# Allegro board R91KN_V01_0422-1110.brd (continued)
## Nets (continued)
GND: C8.2(B) C14.2(B) C20.2(B) C21.2(B) C27.2(B) C33.2(B) C34.1(A) C35.2(B) C43.2(B) C44.2(B) C47.2(B) C53.1(A) C57.2(B) C58.2(B) C59.2(B) C61.2(B) C62.2(B) C63.2(B) C64.2(B) C66.2(B) C67.2(B) C68.2(B) C70.2(B) C71.2(B) C73.2(B) C74.2(B) C75.2(B) C77.2(B) C78.2(B) C79.2(B) C80.2(B) C82.2(B) C83.2(B) C85.2(B) C86.2(B) C87.2(B) C88.2(B) C89.2(B) C90.2(B) C91.2(B) C92.2(B) C93.2(B) C120.2(B) C121.2(B) C122.2(B) C123.2(B) C124.2(B) C125.2(B) C126.2(B) C127.2(B) C128.2(B) C129.2(B) C130.2(B) C131.2(B) C132.2(B) C133.2(B) C134.2(B) C135.2(B) C136.2(B) C137.2(B) C138.2(B) C139.2(B) C140.2(B) C141.2(B) C142.2(B) C143.2(B) C144.2(B) C145.2(B) C146.2(B) C147.2(B) C148.2(B) C149.2(B) C150.2(B) C151.2(B) C152.2(B) C153.2(B) C154.2(B) C155.2(B) C156.2(B) C158.2(B) C161.2(B) C162.2(B) C163.2(B) C164.2(B) C165.2(B) C167.2(B) C168.2(B) C169.2(B) C170.2(B) C171.2(B) C172.2(B) C173.2(B) C174.2(B) C175.2(B) C176.2(B) C177.2(B) C179.2(B) C180.2(B) C181.2(B) C182.2(B) C183.2(B) C184.2(B) C185.2(B) C186.2(B) C187.2(B) C188.2(B) C189.2(B) C190.2(B) C193.2(B) C194.2(B) C195.2(B) C196.2(B) C295.2(B) C297.2(B) C300.1(A) C301.1(A) C302.1(A) C303.1(A) C304.1(A) C305.1(A) C306.1(A) C307.1(A) C308.1(A) C309.1(A) C310.1(A) C311.1(A) C312.1(A) C313.1(A) C314.1(A) C315.1(A) C316.1(A) C317.1(A) C318.1(A) C319.1(A) C320.1(A) C321.1(A) C322.1(A) C323.1(A) C324.1(A) C325.1(A) C326.1(A) C327.1(A) C328.1(A) C329.1(A) C330.1(A) C331.1(A) C332.1(A) C333.1(A) C334.1(A) C335.1(A) C336.1(A) C337.1(A) C338.1(A) C339.1(A) C340.1(A) C341.1(A) C342.1(A) C343.1(A) C344.1(A) C345.1(A) C346.1(A) C347.1(A) C348.1(A) C349.1(A) C350.1(A) C351.1(A) C352.1(A) C353.1(A) C354.1(A) C355.2(B) C356.2(B) C357.2(B) C358.2(B) C359.2(B) C360.2(B) C361.2(B) C362.2(B) C363.2(B) C364.2(B) C365.2(B) C366.2(B) C367.2(B) C368.2(B) C369.2(B) C370.2(B) C371.2(B) C372.2(B) C373.2(B) C374.2(B) C375.2(B) C376.2(B) C377.2(B) C378.2(B) C379.2(B) C380.2(B) C381.2(B) C382.2(B) C383.2(B) C384.1(A) C385.1(A) C386.1(A) C410.2 C411.2 C413.2(B) C438.2(B) C448.2(B) C463.2(B) C486.2(B) C487.2(B) C488.2(B) C489.2(B) C499.2(B) C500.2(B) C603.2(B) C606.2(B) C608.1(A) C609.2(B) C615.2(B) C616.2(B) C617.2(B) C619.2(B) C620.2(B) C621.2(B) C623.2(B) C624.2(B) C625.2(N) C626.2(N) C629.2(B) C630.2(B) C631.2(N) C633.2(B) C703.2(B) C706.2(B) C708.2(B) C715.2(B) C716.2(B) C717.2(B) C718.2(B) C719.2(B) C723.2(B) C724.2(B) C725.2(B) C726.2(N) C727.2(B) C728.1(A) C729.2(N) C730.2(N) C800.1(A) C801.1(A) C841.2(B) C843.2(B) C846.2(B) C851.2(B) C852.2(B) C854.2(B) C856.2(B) C858.2(B) C861.2(B) C862.2(B) C864.2(B) C866.2(B) C868.2(B) C1001.2(B) C1002.2(B) C1003.2(B) C1004.2(B) C1005.2(B) C1006.2(B) C1007.2(B) C1008.2(B) C1010.2(B) C1011.2(B) C1050.2(B) C1051.2(B) C1052.2(B) C1054.2(B) C1055.2(B) C1500.2(B) C1501.1(A) C1502.1(A) C1503.2(B) C1504.1(A) C1505.1(A) C1506.2(B) C1507.1(A) C1508.1(A) C1624.2(B) C1999.1(A) C2001.2(B) C2002.2(B) C2003.2(B) C2004.2(B) C2005.2(B) C2006.2(B) C2509.2(B) C2510.1(A) C2511.1(A) C2512.2(B) C2513.1(A) C2514.1(A) C2515.2(B) C2516.1(A) C2517.1(A) C2540.2(B) C2722.2(B) C3600.2(B) C3608.2(B) C4001.2(B) C4002.2(B) C4003.2(B) C4008.2(B) C4015.2(B) C4020.2(B) C4070.2(B) C4071.2(B) C4100.2(B) C4102.2(B) C4400.2(B) C4401.2(B) C4402.2(B) D1000.2(A) D1001.2(A) D1002.2(A) D1003.2(A) D1004.2(A) D1005.2(A) D1006.2(A) D1600.3(GND) D1600.8(GND1) D1601.3(GND) D1601.8(GND1) D1602.3(GND) D1602.8(GND1) D1603.3(GND) D1603.8(GND1) D2500.2(A) D2501.2(A) D2502.2(A) D2503.3(GND) D2503.8(GND1) D2504.3(GND) D2504.8(GND1) D4401.3(GND) D4401.8(GND1) D4402.3(GND) D4402.8(GND1) D4403.2(A) D4404.2(A) D4405.2(A) D4406.2(A) HS2.1(P1) HS2.2(P2) HS2.3(P3) HS2.4(P4) HS2.5(P5) HS2.6(P6) HS2.7(P7) HS2.8(P8) HS2.9(P1) HS2.10(P2) HS2.11(P3) HS2.12(P4) HS2.13(P5) HS2.14(P6) HS2.15(P7) HS2.16(P8) HS2.17(P1) HS2.18(P2) HS2.19(P3) HS2.20(P4) HS2.21(P5) HS2.22(P6) HS2.23(P7) HS2.24(P8) HS2.25(P1) HS2.26(P2) HS2.27(P3) HS2.28(P4) HS2.29(P5) HS2.30(P6) HS2.31(P7) HS2.32(P8) J1601.3(TMDS_DATA2/4_SHIELD) J1601.11(TMDS_DATA1/3_SHIELD) J1601.15(GND[0]) J1601.19(TMDS_DATA0/5_SHIELD) J1601.22(TMDS_CLOCK_SHIELD) J1601.25(CASE) J1601.26(CASE#M2) J1601.27(CASE#M3) J1601.28(CASE#M4) J1601.29(CASE#M5) J1601.30(CASE#M6) J1601.C5(ANALOG_GND) J1601.C6(ANALOG_GND#C6) J2501.2(GND_0) J2501.5(GND_1) J2501.8(GND_2) J2501.11(GND_3) J2501.16(GND_6) J2501.19(PWR_RTN) J2501.G1 J2501.G2 J2501.G3 J2501.G4 J4004.4(P4) MC130.2(B) MC131.2(B) MC132.2(B) MC133.2(B) MC174.2(B) MC175.2(B) MC176.2(B) MC177.2(B) MC196.2(B) MC364.2(B) MC365.2(B) MC366.2(B) MC367.2(B) MC368.2(B) MC369.2(B) MC378.2(B) MC379.2(B) MC380.2(B) MC381.2(B) MC382.2(B) MC383.2(B) MJ1001.5(VSS) MJ1001.6(VSS#6) MJ1001.7(VSS#7) MJ1001.8(VSS#8) MJ1001.10(VSS#10) MJ1001.16(CASE) MJ1001.17(CASE#17) MJ2501.2 MJ2501.5 MJ2501.8 MJ2501.11 MJ2501.17 MJ2501.20(GND#20) MJ2501.21(GND#21) MJ2501.22(GND#22) MJ2501.23(GND#23) MPCIE1.A4(GND_A4) MPCIE1.A12(GND_A12) MPCIE1.A15(GND_A15) MPCIE1.A18(GND_A18) MPCIE1.A20(GND_A20) MPCIE1.A23(GND_A23) MPCIE1.A24(GND_A24) MPCIE1.A27(GND_A27) MPCIE1.A28(GND_A28) MPCIE1.A31(GND_A31) MPCIE1.A34(GND_A34) MPCIE1.A37(GND_A37) MPCIE1.A38(GND_A38) MPCIE1.A41(GND_A41) MPCIE1.A42(GND_A42) MPCIE1.A45(GND_A45) MPCIE1.A46(GND_A46) MPCIE1.A49(GND_A49) MPCIE1.A51(GND_A51) MPCIE1.A54(GND_A54) MPCIE1.A55(GND_A55) MPCIE1.A58(GND_A58) MPCIE1.A59(GND_A59) MPCIE1.A62(GND_A62) MPCIE1.A63(GND_A63) MPCIE1.A66(GND_A66) MPCIE1.A67(GND_A67) MPCIE1.A70(GND_A70) MPCIE1.A71(GND_A71) MPCIE1.A74(GND_A74) MPCIE1.A75(GND_A75) MPCIE1.A78(GND_A78) MPCIE1.A79(GND_A79) MPCIE1.A82(GND_A82) MPCIE1.B4(GND_B4) MPCIE1.B7(GND_B7) MPCIE1.B13(GND_B13) MPCIE1.B16(GND_B16) MPCIE1.B18(GND_B18) MPCIE1.B21(GND_B21) MPCIE1.B22(GND_B22) MPCIE1.B25(GND_B25) MPCIE1.B26(GND_B26) MPCIE1.B29(GND_B29) MPCIE1.B32(GND_B32) MPCIE1.B35(GND_B35) MPCIE1.B36(GND_B36) MPCIE1.B39(GND_B39) MPCIE1.B40(GND_B40) MPCIE1.B43(GND_B43) MPCIE1.B44(GND_B44) MPCIE1.B47(GND_B47) MPCIE1.B49(GND_B49) MPCIE1.B52(GND_B52) MPCIE1.B53(GND_B53) MPCIE1.B56(GND_B56) MPCIE1.B57(GND_B57) MPCIE1.B60(GND_B60) MPCIE1.B61(GND_B61) MPCIE1.B64(GND_B64) MPCIE1.B65(GND_B65) MPCIE1.B68(GND_B68) MPCIE1.B69(GND_B69) MPCIE1.B72(GND_B72) MPCIE1.B73(GND_B73) MPCIE1.B76(GND_B76) MPCIE1.B77(GND_B77) MPCIE1.B80(GND_B80) MR43.1(A) MR44.1(A) MR45.1(A) MR46.1(A) MR47.1(A) MR48.1(A) MR49.1(A) MR50.1(A) MR51.1(A) MR52.1(A) MR53.1(A) MR54.1(A) MR55.1(A) MR56.1(A) MR57.2(B) MR58.1(A) MR70.1(A) MR71.1(A) MR1240.1(A) MR1241.1(A) MT200.1(P2) MT200.2(P3) MT200.3(P4) MT200.4(P5) MT200.5(P6) MT200.6(P7) MT200.7(P8) MT200.8(P9) MU861.8(GND#8) MU861.9(GND#9) Q603.1(S1) Q603.2(S2) Q603.3(S3) Q703.1(S1) Q703.2(S2) Q703.3(S3) Q840.2(E) Q841.2(E) Q842.2(E) Q851.2(E) Q852.2(E) Q1200.2(S) Q1201.2(S) Q1601.2(S) Q1803.2(E) Q1804.2(S) Q2701.2(S) Q4006.2(E) Q4007.2(E) Q4009.2(E) Q4010.2(E) Q4011.2(E) Q4013.2(E) Q4016.2(E) Q4050.2(E) Q4100.2(E) Q4102.3(C) Q4103.3(E) Q4401.2(E) R7.1(A) R9.2(B) R12.1(A) R22.1(A) R23.2(B) R32.1(A) R35.2(B) R37.2(B) R39.2(B) R60.2(B) R76.1(A) R202.2(B) R204.2(B) R206.2(B) R208.2(B) R210.2(B) R212.2(B) R214.2(B) R216.2(B) R217.2(B) R218.2(B) R219.2(B) R220.2(B) R229.1(A) R230.1(A) R292.2(B) R294.2(B) R296.2(B) R297.2(B) R298.2(B) R301.2(B) R609.1(A) R610.1(A) R615.2(B) R709.1(A) R710.2(B) R715.2(B) R851.2(B) R853.2(B) R854.2(B) R864.2(B) R1001.2(B) R1002.2(B) R1003.2(B) R1027.2(B) R1028.2(B) R1029.2(B) R1500.2(B) R1617.2(B) R2001.2(B) R2002.2(B) R2003.2(B) R2027.2(B) R2028.2(B) R2029.2(B) R2500.2(B) R2522.2(B) R2524.2(B) R2526.2(B) R2530.2(B) R3600.1(A) R4039.2(B) R4043.2(B) R4047.2(B) R4053.2(B) R4061.1(A) R4063.2(B) R4072.2(B) R4073.2(B) R4076.2(B) R4077.2(B) R4106.2(B) R4108.2(B) R4110.2(B) R4111.2(B) R4113.2(B) R4403.2(B) R4408.1(A) R4409.2(B) SW4001.3(A2) SW4001.4(A2) SW4002.3(A2) TP503.1 U1.A3(GND#1) U1.A30(GND#2) U1.A32(VSS_MECH#1) U1.AA1(DP_VSSR#AA1) U1.AA13(GND#3) U1.AA16(GND#84) U1.AA27(PCIE_VSS#1) U1.AB6(GND#6) U1.AB10(GND#4) U1.AB15(GND#5) U1.AB24(PCIE_VSS#2) U1.AB32(PCIE_VSS#3) U1.AC9(GND#7) U1.AC17(TSVSS) U1.AC19(NC#AC19) U1.AC24(PCIE_VSS#4) U1.AC26(PCIE_VSS#5) U1.AC27(PCIE_VSS#6) U1.AD6(GND#8) U1.AD8(GND#9) U1.AD23(VSS1DI) U1.AD25(PCIE_VSS#7) U1.AD32(PCIE_VSS#8) U1.AE1(DP_VSSR#AE1) U1.AE3(DP_VSSR#AE3) U1.AE7(GND#10) U1.AE14(DPLL_PVSS) U1.AE19(TSVSSQ) U1.AE22(AVSSQ) U1.AE27(PCIE_VSS#9) U1.AF10(DP_VSSR#AF10) U1.AF19(DP_VSSR#AF19) U1.AF20(DP_VSSR#AF20) U1.AF23(DP_VSSR#AF23) U1.AF32(PCIE_VSS#10) U1.AG1(DP_VSSR#AG1) U1.AG6(DP_VSSR#AG6) U1.AG7(DP_VSSR#AG7) U1.AG9(DP_VSSR#AG9) U1.AG11(DP_VSSR#AG11) U1.AG12(GND#11) U1.AG14(DP_VSSR#AG14) U1.AG23(DP_VSSR#AG23) U1.AG27(PCIE_VSS#11) U1.AH5(DP_VSSR#AH5) U1.AH8(DP_VSSR#AH8) U1.AH10(GND#12) U1.AH14(DP_VSSR#AH14) U1.AH28(GND#13) U1.AH32(PCIE_VSS#12) U1.AM1(VSS_MECH#2) U1.AM6(DP_VSSR#AM6) U1.AM8(DP_VSSR#AM8) U1.AM14(DP_VSSR#AM14) U1.AM16(DP_VSSR#AM16) U1.AM18(DP_VSSR#AM18) U1.AM20(DP_VSSR#AM20) U1.AM22(DP_VSSR#AM22) U1.AM24(DP_VSSR#AM24) U1.AM32(VSS_MECH#3) U1.B6(GND#23) U1.B8(GND#24) U1.B10(GND#14) U1.B12(GND#15) U1.B14(GND#16) U1.B16(GND#17) U1.B18(GND#18) U1.B20(GND#19) U1.B22(GND#20) U1.B24(GND#21) U1.B26(GND#22) U1.C1(GND#25) U1.C32(GND#26) U1.E28(GND#27) U1.F2(GND#33) U1.F6(GND#38) U1.F8(GND#39) U1.F10(GND#28) U1.F12(GND#29) U1.F14(GND#30) U1.F16(GND#31) U1.F18(GND#32) U1.F20(GND#34) U1.F22(GND#35) U1.F24(GND#36) U1.F26(GND#37) U1.G8(GND#43) U1.G10(GND#40) U1.G27(GND#41) U1.G31(GND#42) U1.H2(GND#46) U1.H6(GND#48) U1.H14(GND#44) U1.H17(GND#45) U1.H20(GND#47) U1.J7(SPVSS) U1.J27(GND#49) U1.J31(GND#50) U1.K2(GND#52) U1.K6(GND#54) U1.K11(GND#51) U1.K22(GND#53) U1.K28(PCIE_VSS#13) U1.K32(PCIE_VSS#14) U1.L27(PCIE_VSS#15) U1.M6(GND#55) U1.M32(PCIE_VSS#16) U1.N11(NC#N11) U1.N12(NC#N12) U1.N13(GND#56) U1.N16(GND#57) U1.N18(GND#58) U1.N21(GND#59) U1.N25(PCIE_VSS#17) U1.N27(PCIE_VSS#18) U1.P6(GND#60) U1.P9(GND#61) U1.P25(PCIE_VSS#19) U1.P32(PCIE_VSS#20) U1.R11(GND#86) U1.R12(GND#62) U1.R15(GND#63) U1.R17(GND#64) U1.R20(GND#65) U1.R27(PCIE_VSS#21) U1.T6(GND#70) U1.T11(GND#85) U1.T13(GND#66) U1.T16(GND#67) U1.T18(GND#68) U1.T21(GND#69) U1.T25(PCIE_VSS#22) U1.T32(PCIE_VSS#23) U1.U1(DP_VSSR#U1) U1.U3(DP_VSSR#U3) U1.U9(GND#74) U1.U15(GND#71) U1.U17(GND#72) U1.U20(GND#73) U1.U25(PCIE_VSS#24) U1.U27(PCIE_VSS#25) U1.V6(DP_VSSR#V6) U1.V13(GND#75) U1.V16(GND#76) U1.V18(GND#77) U1.V32(PCIE_VSS#26) U1.W1(DP_VSSR#W1) U1.W25(PCIE_VSS#27) U1.W26(PCIE_VSS#28) U1.W27(PCIE_VSS#29) U1.Y6(DP_VSSR#Y6) U1.Y10(GND#78) U1.Y15(GND#79) U1.Y17(GND#80) U1.Y20(GND#81) U1.Y25(PCIE_VSS#30) U1.Y32(PCIE_VSS#31) U2.4(GND) U4.3(GND) U12.2(GND_27M) U12.6(GND_100M) U12.11(GND_PAD) U201.A9(VSS#A9) U201.B1(VSSQ#B1) U201.B3(VSS#B3) U201.B9(VSSQ#B9) U201.D1(VSSQ#D1) U201.D8(VSSQ#D8) U201.E1(VSS#E1) U201.E2(VSSQ#E2) U201.E8(VSSQ#E8) U201.F9(VSSQ#F9) U201.G1(VSSQ#G1) U201.G8(VSS#G8) U201.G9(VSSQ#G9) U201.J2(VSS#J2) U201.J8(VSS#J8) U201.M1(VSS#M1) U201.M9(VSS#M9) U201.P1(VSS#P1) U201.P9(VSS#P9) U201.T1(VSS#T1) U201.T9(VSS#T9) U202.A9(VSS#A9) U202.B1(VSSQ#B1) U202.B3(VSS#B3) U202.B9(VSSQ#B9) U202.D1(VSSQ#D1) U202.D8(VSSQ#D8) U202.E1(VSS#E1) U202.E2(VSSQ#E2) U202.E8(VSSQ#E8) U202.F9(VSSQ#F9) U202.G1(VSSQ#G1) U202.G8(VSS#G8) U202.G9(VSSQ#G9) U202.J2(VSS#J2) U202.J8(VSS#J8) U202.M1(VSS#M1) U202.M9(VSS#M9) U202.P1(VSS#P1) U202.P9(VSS#P9) U202.T1(VSS#T1) U202.T9(VSS#T9) U401.A9(VSS#A9) U401.B1(VSSQ#B1) U401.B3(VSS#B3) U401.B9(VSSQ#B9) U401.D1(VSSQ#D1) U401.D8(VSSQ#D8) U401.E1(VSS#E1) U401.E2(VSSQ#E2) U401.E8(VSSQ#E8) U401.F9(VSSQ#F9) U401.G1(VSSQ#G1) U401.G8(VSS#G8) U401.G9(VSSQ#G9) U401.J2(VSS#J2) U401.J8(VSS#J8) U401.M1(VSS#M1) U401.M9(VSS#M9) U401.P1(VSS#P1) U401.P9(VSS#P9) U401.T1(VSS#T1) U401.T9(VSS#T9) U402.A9(VSS#A9) U402.B1(VSSQ#B1) U402.B3(VSS#B3) U402.B9(VSSQ#B9) U402.D1(VSSQ#D1) U402.D8(VSSQ#D8) U402.E1(VSS#E1) U402.E2(VSSQ#E2) U402.E8(VSSQ#E8) U402.F9(VSSQ#F9) U402.G1(VSSQ#G1) U402.G8(VSS#G8) U402.G9(VSSQ#G9) U402.J2(VSS#J2) U402.J8(VSS#J8) U402.M1(VSS#M1) U402.M9(VSS#M9) U402.P1(VSS#P1) U402.P9(VSS#P9) U402.T1(VSS#T1) U402.T9(VSS#T9) U403.2(GND) U403.4(TAB) U601.3(GND) U701.3(GND) U851.8(GND#8) U851.9(GND#9) U861.8(GND#8) U861.9(GND#9) U1999.1(C) U1999.4(C) U1999.7(GND) U4001.6(GND) U4001.11(EPAD1) U4050.3(GND) U4050.15(EPAD)
VDD33_27M: B72.2(B) C90.1(A) U12.8(VDD_27M)
VDD33_100M: B71.2(B) C91.1(A) U12.4(VDD_100M)
VDDC_BOOT: C605.1(A) D601.1(K) U601.1(BOOT)
VDDC_EN: C611.1(A) C612.1(A) Q852.3(C) Q4010.3(C) U601.7(COMP)
VDDC_ENB: C4401.1(A) Q4010.1(B) R4051.1(A) R4053.1(A)
VDDC_FB: R610.2(B) R611.1(A) R613.1(A) R614.1(A) R1225.1(A) R1226.1(A) R4078.2(B) U601.6(FB)
VDDC_FB_IN1: Q1200.3(D) R1226.2(B)
VDDC_FB_IN2: Q1201.3(D) R1225.2(B)
VDDC_FB_TRACE: NS600.2(N2) R600.1(A)
VDDC_LGATE: Q603.4(G4) R622.2(B)
VDDC_LGATE_CTR: R615.1(A) R622.1(A) U601.4(LGATE)
VDDC_PHASE: C605.2(B) L601.1 Q601.1(S1) Q601.2(S2) Q601.3(S3) Q603.5(D5) Q603.6(D6) Q603.7(D7) Q603.8(D8) Q603.9(D9) R619.2(B) U601.8(PHASE)
VDDC_SV: C613.1(A) R600.2(B) R611.2(B)
VDDC_UGATE: Q601.4(G4) R621.2(B)
VDDC_UGATE_CTR: R621.1(A) U601.2(UGATE)
VDDC_VCC: C603.1(A) R607.2(B) U601.5(VCC)
+DPAB_18: B2503.2(B) C2509.1(A) C2510.2(B) C2511.2(B) C2512.1(A) C2513.2(B) C2514.2(B) U1.AE11(DPAB_VDD18#3) U1.AE13(DPAB_VDD18#5) U1.AF11(DPAB_VDD18#4) U1.AF13(DPAB_VDD18#6) U1.AG8(DPAB_VDD18#1) U1.AG10(DPAB_VDD18#2)
+DPAB_VDD10: B2505.2(B) C2515.1(A) C2516.2(B) C2517.2(B) U1.AF6(DPAB_VDD10#1) U1.AF7(DPAB_VDD10#2) U1.AF8(DPAB_VDD10#3) U1.AF9(DPAB_VDD10#4)
+DPC_18: B800.2(B) C800.2(B) U1.AC5(DPC_VDD18#2) U1.AC6(DPC_VDD18#3) U1.W6(DPC_VDD18#1)
+DPC_VDD10: B801.2(B) C801.2(B) U1.AA5(DPC_VDD10#1) U1.AA6(DPC_VDD10#2)
+DPEF_18: B1500.2(B) C1500.1(A) C1501.2(B) C1502.2(B) C1503.1(A) C1504.2(B) C1505.2(B) U1.AF16(DPEF_VDD18#5) U1.AG15(DPEF_VDD18#3) U1.AG16(DPEF_VDD18#4) U1.AG17(DPEF_VDD18#6) U1.AG18(DPEF_VDD18#1) U1.AG19(DPEF_VDD18#2)
+DPEF_VDD10: B1502.2(B) C1506.1(A) C1507.2(B) C1508.2(B) U1.AF22(DPEF_VDD10#3) U1.AG20(DPEF_VDD10#1) U1.AG21(DPEF_VDD10#2) U1.AG22(DPEF_VDD10#4)
+DPLL_PVDD: B7.2(B) C59.1(A) C63.1(A) C64.1(A) C88.1(A) U1.AF14(DPLL_PVDD)
+DPLL_VDDC: B8.2(B) C66.1(A) C67.1(A) C68.1(A) U1.AD14(DPLL_VDDC)
+MPV18: B12.2(B) C77.1(A) C78.1(A) C79.1(A) C80.1(A) U1.L8(MPV18)
+MVDD: C120.1(A) C121.1(A) C122.1(A) C123.1(A) C124.1(A) C125.1(A) C126.1(A) C127.1(A) C128.1(A) C129.1(A) C130.1(A) C131.1(A) C132.1(A) C133.1(A) C134.1(A) C135.1(A) C136.1(A) C137.1(A) C138.1(A) C139.1(A) C140.1(A) C141.1(A) C142.1(A) C300.2(B) C301.2(B) C302.2(B) C303.2(B) C304.2(B) C305.2(B) C306.2(B) C307.2(B) C308.2(B) C309.2(B) C310.2(B) C311.2(B) C312.2(B) C313.2(B) C314.2(B) C315.2(B) C316.2(B) C317.2(B) C318.2(B) C319.2(B) C320.2(B) C321.2(B) C322.2(B) C323.2(B) C324.2(B) C325.2(B) C326.2(B) C327.2(B) C328.2(B) C329.2(B) C330.2(B) C331.2(B) C332.2(B) C333.2(B) C334.2(B) C335.2(B) C336.2(B) C337.2(B) C338.2(B) C339.2(B) C340.2(B) C341.2(B) C342.2(B) C343.2(B) C344.2(B) C345.2(B) C346.2(B) C347.2(B) C348.2(B) C349.2(B) C350.2(B) C351.2(B) C352.2(B) C353.2(B) C354.2(B) C355.1(A) C356.1(A) C357.1(A) C358.1(A) C359.1(A) C360.1(A) C361.1(A) C362.1(A) C363.1(A) C364.1(A) C365.1(A) C366.1(A) C367.1(A) C368.1(A) C369.1(A) C370.1(A) C371.1(A) C372.1(A) C373.1(A) C374.1(A) C375.1(A) C376.1(A) C377.1(A) C378.1(A) C379.1(A) C380.1(A) C381.1(A) C382.1(A) C383.1(A) C384.2(B) C385.2(B) C386.2(B) C723.1(A) C724.1(A) C725.1(A) C726.1(P) C727.1(A) C728.2(B) C729.1(P) L701.2 MC130.1(A) MC131.1(A) MC132.1(A) MC133.1(A) MC364.1(A) MC365.1(A) MC366.1(A) MC367.1(A) MC368.1(A) MC369.1(A) MC378.1(A) MC379.1(A) MC380.1(A) MC381.1(A) MC382.1(A) MC383.1(A) MR858.1(A) NS700.1(N1) R201.1(A) R203.1(A) R205.1(A) R207.1(A) R209.1(A) R211.1(A) R213.1(A) R215.1(A) R225.2(B) R227.2(B) R291.1(A) R293.1(A) R302.2(B) R858.1(A) U1.H13(VDDR1#1) U1.H16(VDDR1#2) U1.H19(VDDR1#3) U1.J9(VDDR1#7) U1.J10(VDDR1#4) U1.J23(VDDR1#5) U1.J24(VDDR1#6) U1.K9(VDDR1#11) U1.K10(VDDR1#8) U1.K23(VDDR1#9) U1.K24(VDDR1#10) U1.L11(VDDR1#12) U1.L12(VDDR1#13) U1.L13(VDDR1#14) U1.L20(VDDR1#15) U1.L21(VDDR1#16) U1.L22(VDDR1#17) U201.A1(VDDQ#A1) U201.A8(VDDQ#A8) U201.B2(VDD#B2) U201.C1(VDDQ#C1) U201.C9(VDDQ#C9) U201.D2(VDDQ#D2) U201.D9(VDD#D9) U201.E9(VDDQ#E9) U201.F1(VDDQ#F1) U201.G7(VDD#G7) U201.H2(VDDQ#H2) U201.H9(VDDQ#H9) U201.K2(VDD#K2) U201.K8(VDD#K8) U201.N1(VDD#N1) U201.N9(VDD#N9) U201.R1(VDD#R1) U201.R9(VDD#R9) U202.A1(VDDQ#A1) U202.A8(VDDQ#A8) U202.B2(VDD#B2) U202.C1(VDDQ#C1) U202.C9(VDDQ#C9) U202.D2(VDDQ#D2) U202.D9(VDD#D9) U202.E9(VDDQ#E9) U202.F1(VDDQ#F1) U202.G7(VDD#G7) U202.H2(VDDQ#H2) U202.H9(VDDQ#H9) U202.K2(VDD#K2) U202.K8(VDD#K8) U202.N1(VDD#N1) U202.N9(VDD#N9) U202.R1(VDD#R1) U202.R9(VDD#R9) U401.A1(VDDQ#A1) U401.A8(VDDQ#A8) U401.B2(VDD#B2) U401.C1(VDDQ#C1) U401.C9(VDDQ#C9) U401.D2(VDDQ#D2) U401.D9(VDD#D9) U401.E9(VDDQ#E9) U401.F1(VDDQ#F1) U401.G7(VDD#G7) U401.H2(VDDQ#H2) U401.H9(VDDQ#H9) U401.K2(VDD#K2) U401.K8(VDD#K8) U401.N1(VDD#N1) U401.N9(VDD#N9) U401.R1(VDD#R1) U401.R9(VDD#R9) U402.A1(VDDQ#A1) U402.A8(VDDQ#A8) U402.B2(VDD#B2) U402.C1(VDDQ#C1) U402.C9(VDDQ#C9) U402.D2(VDDQ#D2) U402.D9(VDD#D9) U402.E9(VDDQ#E9) U402.F1(VDDQ#F1) U402.G7(VDD#G7) U402.H2(VDDQ#H2) U402.H9(VDDQ#H9) U402.K2(VDD#K2) U402.K8(VDD#K8) U402.N1(VDD#N1) U402.N9(VDD#N9) U402.R1(VDD#R1) U402.R9(VDD#R9) UNK+MVDD.1
+MVDD_SOURCE: B702.1(A) C715.1(A) C716.1(A) C717.1(A) C718.1(A) C719.1(A) C730.1(P) Q701.5(D5) Q701.6(D6) Q701.7(D7) Q701.8(D8) Q701.9(D9) R702.1(A)
+PCIE_PVDD: B11.2(B) C73.1(A) C74.1(A) C75.1(A) C89.1(A) U1.AM30(PCIE_VDDR#9)
+SPV10: B9.2(B) C70.1(A) C71.1(A) MB9.2(B) U1.H8(SPV10)
+SPV18: B5.2(B) C58.1(A) C61.1(A) C62.1(A) U1.H7(SPV18)
A_B_DAC1: MR1017.1(A) R1001.1(A) R1017.1(A) U1.AH24(B)
A_B_DAC1_F: C1006.1(A) D1002.1(K) J1601.C3(ANALOG_BLUE) L1003.2(B)
A_B_DAC2_F: C2006.1(A) L2003.2(B) MJ1001.3(B)
A_BB_DAC1: MR1029.1(A) R1029.1(A) U1.AG25(BB)
A_G_DAC1: MR1016.1(A) R1002.1(A) R1016.1(A) U1.AL25(G)
A_G_DAC1_F: C1005.1(A) D1001.1(K) J1601.C2(ANALOG_GREEN) L1002.2(B)
A_G_DAC2_F: C2005.1(A) L2002.2(B) MJ1001.2(G)
A_GB_DAC1: MR1028.1(A) R1028.1(A) U1.AJ25(GB)
A_HSYNC_DAC1: MR52.2(B) R52.2(B) U1.AH26(HSYNC) U1999.2(A)
A_HSYNC_DAC1_B: R1010.1(A) U1999.3(Y)
A_HSYNC_DAC1_C: C1007.1(A) MR1018.1(A) R1010.2(B) R1018.1(A)
A_HSYNC_DAC1_R: D1005.1(K) J1601.C4(ANALOG_HYNC) R1018.2(B)
A_HSYNC_DAC2: MR56.2(B) R56.2(B) U1.AL13(GENLK_CLK)
A_HSYNC_DAC2_R: MJ1001.13(HS) MR1018.2(B)
A_R_DAC1: MR1015.1(A) R1003.1(A) R1015.1(A) U1.AM26(R)
A_R_DAC1_F: C1004.1(A) D1000.1(K) J1601.C1(ANALOG_RED) L1001.2(B)
A_R_DAC2_F: C2004.1(A) L2001.2(B) MJ1001.1(R)
A_RB_DAC1: MR1027.1(A) R1027.1(A) U1.AK26(RB)
A_VSYNC_DAC1: MR51.2(B) R51.2(B) U1.AJ27(VSYNC) U1999.5(A)
A_VSYNC_DAC1_B: R1011.1(A) U1999.6(Y)
A_VSYNC_DAC1_C: C1008.1(A) MR1019.1(A) R1011.2(B) R1019.1(A)
A_VSYNC_DAC1_R: D1006.1(K) J1601.8(ANALOG_VSYNC) R1019.2(B)
A_VSYNC_DAC2: MR43.2(B) R43.2(B) U1.AJ13(GENLK_VSYNC)
A_VSYNC_DAC2_R: MJ1001.14(VS) MR1019.2(B)
AUX1_BYPSS_EN: Q1801.1(G) Q1802.1(G) Q1803.3(C) R1804.2(B)
AUX2N: C2541.1(A) U1.AD11(AUX2N)
AUX2P: C2535.1(A) U1.AD13(AUX2P)
B_DAC2: C2003.1(A) L2003.1(A) MR1017.2(B) R2001.1(A)
BA0: U1.J16(MAA_BA0) U201.M2(BA0) U202.M2(BA0) U401.M2(BA0) U402.M2(BA0)
BA1: U1.L15(MAA_BA1) U201.N8(BA1) U202.N8(BA1) U401.N8(BA1) U402.N8(BA1)
BA2: U1.G11(MAA_BA2) U201.M3(BA2) U202.M3(BA2) U401.M3(BA2) U402.M3(BA2)
BB_DAC2: MR1029.2(B) R2029.1(A)
CASA#0: U1.G19(CASA0B) U201.K3(CAS_N) U202.K3(CAS_N)
CASA#1: U1.G16(CASA1B) U401.K3(CAS_N) U402.K3(CAS_N)
CEC1: MJ2501.13 TP1700.1
CEDAR_NC: R72.1(A) U1.AA11(NC#1) U1.AA12(NC#4) U1.U11(NC#3) U1.V11(NC#2) U1.Y11(DVCLK)
CKEA0: U1.K20(CKEA0) U201.K9(CKE) U202.K9(CKE)
CKEA1: U1.J17(CKEA1) U401.K9(CKE) U402.K9(CKE)
CLK_27M: MR75.1(A) NR75.1(A) TR75.1(A) U12.9(27M_OUT)
CLK_100M: R73.1(A) R74.1(A) R75.1(A) U12.5(100M_OUT)
CLKA0: R221.1(A) U1.H26(CLKA0) U201.J7(CK) U202.J7(CK)
CLKA1: R223.1(A) U1.G9(CLKA1) U401.J7(CK) U402.J7(CK)
CLKA#0: R222.2(B) U1.H25(CLKA0B) U201.K7(CK_N) U202.K7(CK_N)
CLKA#1: R224.2(B) U1.H9(CLKA1B) U401.K7(CK_N) U402.K7(CK_N)
CLKTESTA: C94.1(A) U1.K8(CLKTESTA)
CLKTESTB: C95.1(A) U1.L7(CLKTESTB)
CSA#0_0: U1.H22(CSA0B_0) U201.L2(CS_N) U202.L2(CS_N)
CSA#1_0: U1.G13(CSA1B_0) U401.L2(CS_N) U402.L2(CS_N)
CTF2_GAT: Q4400.1(B) R4405.1(A) R4407.2(B)
CTF2_TRIP: C4400.1(A) Q4401.1(B) R4402.1(A) R4403.1(A) R4404.2(B)
CTF2_VCNTL: Q4400.3(C) R4404.1(A) R4406.1(A)
CTF_BYPASS: R4051.2(B) R4052.2(B) R4057.2(B) R4058.2(B) R4062.2(B) R4406.2(B) R4408.2(B)
CTF_FB_CNTL: Q4007.1(B) R4046.1(A)
CTF_GATED2: Q4006.3(C) Q4007.3(C) R4040.2(B) R4044.2(B) R4065.2(B)
CTF_SET2: C4013.2(B) C4014.2(B) Q4008.1(B) Q4014.2(S) R4043.1(A)
CTF_SET3: Q4009.1(B) R4044.1(A)
CTF_TRIP: Q4006.1(B) R4038.2(B) R4039.1(A)
CTF_VCNTL: C4015.1(A) Q4009.3(C) R4045.2(B) R4046.2(B) R4047.1(A) R4052.1(A) R4060.1(A)
CUR_VDDCT_ADJ_0: R4078.1(A) U4050.8(OUT0)
DACT_A0: R4077.1(A) U4050.9(A0)
DACT_A1: MR4076.2(B) R4076.1(A) U4050.11(A1)
DACT_CLK: R4071.2(B) U4050.2(SCL)
DACT_DATA: R4070.2(B) U4050.1(SDA)
DACT_FS0: R4073.1(A) U4050.7(FS0)
DACT_FS1: R4072.1(A) U4050.6(FS1)
DDC1CLK: R2008.2(B) R2009.1(A) U1.AE6(DDC1CLK)
DDC1DATA: R2005.2(B) R2006.1(A) U1.AE5(DDC1DATA)
DDC2CLK: Q1801.2(S) U1.AC11(DDC2CLK)
DDC2DATA: Q1802.2(S) U1.AC13(DDC2DATA)
DDC3CLK: R1008.2(B) R1009.1(A) U1.AD20(DDCCLK_AUX3P)
DDC3DATA: R1005.2(B) R1006.1(A) U1.AC20(DDCDATA_AUX3N)
DDC5CLK_AUX5P: D4404.1(K) MJ2501.15 R2701.2(B) U1.AE16(DDCCLK_AUX5P)
DDC5DATA_AUX5N: D4403.1(K) MJ2501.16 R2703.2(B) U1.AD16(DDCDATA_AUX5N)
DDC6CLK: R4001.1(A) R4017.2(B) R4071.1(A) U1.AC1(DDC6CLK)
DDC6DATA: R4002.1(A) R4018.2(B) R4070.1(A) U1.AC3(DDC6DATA)
DDCCLK_DAC1_R: D1004.1(K) J1601.6(DDC_CLOCK) R1009.2(B)
DDCCLK_DAC2_R: MJ1001.15(MS3) R2009.2(B)
DDCDATA_DAC1_R: D1003.1(K) J1601.7(DDC_DATA) R1006.2(B)
DDCDATA_DAC2_R: MJ1001.12(MS1) R2006.2(B)
DPA_0N: C4404.2(B) D4401.4(C) D4401.7(Y3) J2501.3(ML_LANE_0N)
DPA_0P: C4403.2(B) D4401.5(D) D4401.6(Y4) J2501.1(ML_LANE_0P)
DPA_1N: C4406.2(B) D4401.1(A) D4401.10(Y1) J2501.6(ML_LANE_1N)
DPA_1P: C4405.2(B) D4401.2(B) D4401.9(Y2) J2501.4(ML_LANE_1P)
DPA_2N: C4408.2(B) D4402.4(C) D4402.7(Y3) J2501.9(ML_LANE_2N)
DPA_2P: C4407.2(B) D4402.5(D) D4402.6(Y4) J2501.7(ML_LANE_2P)
DPA_3N: C4410.2(B) D4402.1(A) D4402.10(Y1) J2501.12(ML_LANE_3N)
DPA_3P: C4409.2(B) D4402.2(B) D4402.9(Y2) J2501.10(ML_LANE_3P)
DPA_A0N: C4404.1(A) U1.AK1(TX2M_DPA0N)
DPA_A0P: C4403.1(A) U1.AK3(TX2P_DPA0P)
DPA_A1N: C4406.1(A) U1.AH1(TX1M_DPA1N)
DPA_A1P: C4405.1(A) U1.AH3(TX1P_DPA1P)
DPA_A2N: C4408.1(A) U1.AG5(TX0M_DPA2N)
DPA_A2P: C4407.1(A) U1.AG3(TX0P_DPA2P)
DPA_A3N: C4410.1(A) U1.AF4(TXCAM_DPA3N)
DPA_A3P: C4409.1(A) U1.AF2(TXCAP_DPA3P)
DPA_GND: Q2701.3(D) R2713.2(B) R2714.2(B) R2715.2(B) R2716.2(B) R2717.2(B) R2718.2(B) R2719.2(B) R2720.2(B)
DPAB_CALR: R2500.1(A) U1.AE10(DPAB_CALR)
DPB_0N: C2531.2(B) D2504.4(C) D2504.7(Y3) MJ2501.3 R2714.1(A)
DPB_0P: C2530.2(B) D2504.5(D) D2504.6(Y4) MJ2501.1 R2713.1(A)
DPB_1M: J2501.14(PIN_14) R2526.1(A)
DPB_1N: C2533.2(B) D2504.1(A) D2504.10(Y1) MJ2501.6 R2716.1(A)
DPB_1P: C2532.2(B) D2504.2(B) D2504.9(Y2) MJ2501.4 R2715.1(A)
DPB_2N: C2536.2(B) D2503.4(C) D2503.7(Y3) MJ2501.9 R2718.1(A)
DPB_2P: C2534.2(B) D2503.5(D) D2503.6(Y4) MJ2501.7 R2717.1(A)
DPB_3N: C2538.2(B) D2503.1(A) D2503.10(Y1) MJ2501.12 R2720.1(A)
DPB_3P: C2537.2(B) D2503.2(B) D2503.9(Y2) MJ2501.10 R2719.1(A)
DPB_AUXN: C2541.2(B) D2500.1(K) J2501.17(AUX_CHN) Q1802.3(D) R2523.2(B)
DPB_AUXP: C2535.2(B) D2501.1(K) J2501.15(AUX_CHP) Q1801.3(D) R2522.1(A)
DPB_C0N: C2531.1(A) U1.AL7(TX5M_DPB0N)
DPB_C0P: C2530.1(A) U1.AK8(TX5P_DPB0P)
DPB_C1N: C2533.1(A) U1.AH6(TX4M_DPB1N)
DPB_C1P: C2532.1(A) U1.AJ7(TX4P_DPB1P)
DPB_C2N: C2536.1(A) U1.AM5(TX3M_DPB2N)
DPB_C2P: C2534.1(A) U1.AK6(TX3P_DPB2P)
DPB_C3N: C2538.1(A) U1.AM3(TXCBM_DPB3N)
DPB_C3P: C2537.1(A) U1.AK5(TXCBP_DPB3P)
DPB_DONGLE_DET: D2502.1(K) J2501.13(PIN_13) Q1804.1(G) R2524.1(A)
DPCD_CALR: R298.1(A) U1.J8(DPC_CALR)
DPE_TX0N: C1606.1(A) U1.AJ15(T2X0M_DPE2N)
DPE_TX0P: C1605.1(A) U1.AH16(T2X0P_DPE2P)
DPE_TX1N: C1604.1(A) U1.AK16(T2X1M_DPE1N)
DPE_TX1P: C1603.1(A) U1.AL17(T2X1P_DPE1P)
DPE_TX2N: C1602.1(A) U1.AJ17(T2X2M_DPE0N)
DPE_TX2P: C1601.1(A) U1.AH18(T2X2P_DPE0P)
DPE_TXCAN: C1608.1(A) U1.AK14(T2XCEM_DPE3N)
DPE_TXCAP: C1607.1(A) U1.AL15(T2XCEP_DPE3P)
DPEF_CALR: R1500.1(A) U1.AF17(DPEF_CALR)
DPEF_GND: Q1601.3(D) R1601.2(B) R1602.2(B) R1603.1(A) R1604.1(A) R1605.1(A) R1606.1(A) R1607.1(A) R1608.1(A) R1609.1(A) R1610.1(A) R1611.1(A) R1612.1(A) R1613.1(A) R1614.1(A)
DPF_TX3N: C1614.1(A) U1.AK20(T2X3M_DPF2N)
DPF_TX3P: C1613.1(A) U1.AL21(T2X3P_DPF2P)
DPF_TX4N: C1612.1(A) U1.AJ21(T2X4M_DPF1N)
DPF_TX4P: C1611.1(A) U1.AH22(T2X4P_DPF1P)
DPF_TX5N: C1610.1(A) U1.AK22(T2X5M_DPF0N)
DPF_TX5P: C1609.1(A) U1.AL23(T2X5P_DPF0P)
DRAM_RST: R3616.1(A) U201.T2(RESET_N) U202.T2(RESET_N) U401.T2(RESET_N) U402.T2(RESET_N)
DRST: C3600.1(A) R3600.2(B) R3615.2(B) U1.L10(DRAM_RST)
DRST_R: C3608.1(A) R3615.1(A) R3616.2(B)
EFTX0M: C1606.2(B) D1602.4(C) D1602.7(Y3) J1601.17(TMDS_DATA0-) R1606.2(B)
EFTX0P: C1605.2(B) D1602.5(D) D1602.6(Y4) J1601.18(TMDS_DATA0+) R1605.2(B)
EFTX1M: C1604.2(B) D1600.1(A) D1600.10(Y1) J1601.9(TMDS_DATA1-) R1604.2(B)
EFTX1P: C1603.2(B) D1600.2(B) D1600.9(Y2) J1601.10(TMDS_DATA1+) R1603.2(B)
EFTX2M: C1602.2(B) D1600.4(C) D1600.7(Y3) J1601.1(TMDS_DATA2-) R1602.1(A)
EFTX2P: C1601.2(B) D1600.5(D) D1600.6(Y4) J1601.2(TMDS_DATA2+) R1601.1(A)
EFTX3M: C1614.2(B) D1603.5(D) D1603.6(Y4) J1601.12(TMDS_DATA3-) R1614.2(B)
EFTX3P: C1613.2(B) D1603.4(C) D1603.7(Y3) J1601.13(TMDS_DATA3+) R1613.2(B)
EFTX4M: C1612.2(B) D1601.1(A) D1601.10(Y1) J1601.4(TMDS_DATA4-) R1612.2(B)
EFTX4P: C1611.2(B) D1601.2(B) D1601.9(Y2) J1601.5(TMDS_DATA4+) R1611.2(B)
EFTX5M: C1610.2(B) D1601.4(C) D1601.7(Y3) J1601.20(TMDS_DATA5-) R1610.2(B)
EFTX5P: C1609.2(B) D1601.5(D) D1601.6(Y4) J1601.21(TMDS_DATA5+) R1609.2(B)
EFTXCM: C1608.2(B) D1602.1(A) D1602.10(Y1) J1601.24(TMDS_CLOCK-) R1608.2(B)
EFTXCP: C1607.2(B) D1602.2(B) D1602.9(Y2) J1601.23(TMDS_CLOCK+) R1607.2(B)
FANOUT_N: C4103.2(B) JU4001.2(P2) Q4103.2(C1) Q4103.4(C2) R4107.2(B) R4110.1(A)
FANOUT_P: B4001.2(B) C4008.1(A) C4103.1(A) JU4001.1(P1)
G1_PMBUS_C: R597.2(B) TP502.1
G1_PMBUS_D: R596.2(B) TP501.1
G_DAC2: C2002.1(A) L2002.1(A) MR1016.2(B) R2002.1(A)
GB_DAC2: MR1028.2(B) R2028.1(A)
GENERICA: R73.2(B) U1.AB13(GENERICA)
GENERICB: R32.2(B) U1.W8(GENERICB)
GENERICC: TP58.1 U1.W9(GENERICC)
GENERICD: TP59.1 U1.W7(GENERICD)
GENERICE_HPD4: Q1602.2(E) R1617.1(A) U1.AD10(GENERICE_HPD4)
GPIO_0: MR45.2(B) R45.2(B) SW4001.1(A1) U1.U6(GPIO_0)
GPIO_1: MR46.2(B) R46.2(B) SW4001.2(A1) U1.U10(GPIO_1)
GPIO_2: MR47.2(B) R47.2(B) SW4002.1(A1) U1.T10(GPIO_2)
GPIO_3_SMBDATA: Q1.2(S) R1.2(B) R3.1(A) U1.U8(GPIO_3_SMBDATA)
GPIO_4_SMBCLK: Q2.2(S) R2.2(B) R4.1(A) U1.U7(GPIO_4_SMBCLK)
GPIO_5: MR54.2(B) R54.2(B) U1.T9(GPIO_5_AC_BATT)
GPIO_6: MR58.2(B) R58.2(B) U1.T8(GPIO_6_TACH)
GPIO_7: MR57.1(A) R57.2(B) U1.T7(GPIO_7)
GPIO_8_R: MR53.2(B) R13.2(B) R53.2(B) U2.2(SO)
GPIO_8_SO: R13.1(A) U1.P10(GPIO_8_ROMSO)
GPIO_9_R: MR44.2(B) R14.2(B) R44.2(B) U2.5(SI)
GPIO_9_SI: R14.1(A) U1.P4(GPIO_9_ROMSI)
GPIO_10_R: R15.2(B) U2.6(SCK)
GPIO_10_SCK: R15.1(A) U1.P2(GPIO_10_ROMSCK)
GPIO_11: MR48.2(B) R48.2(B) U1.N6(GPIO_11)
GPIO_12: MR50.2(B) R50.2(B) U1.N5(GPIO_12)
GPIO_13: MR49.2(B) R49.2(B) U1.N3(GPIO_13)
GPIO_14_HPD2: Q2513.2(E) R2530.1(A) U1.Y9(GPIO_14_HPD2)
GPIO_15_PWRCNTL_0: MR1240.2(B) Q1200.1(G) R1240.1(A) U1.N1(GPIO_15_PWRCNTL_0)
GPIO_16: MR55.2(B) R55.2(B) U1.M4(GPIO_16)
GPIO_17_THERMINT: R4011.2(B) R4080.1(A) R4401.2(B) U1.R6(GPIO_17_THERMAL_INT)
GPIO_18_HPD3: TP97.1 U1.W10(GPIO_18_HPD3)
GPIO_19_CTF: R4038.1(A) R4062.1(A) R4400.2(B) U1.M2(GPIO_19_CTF)
GPIO_20_PWRCNTL_1: MR1241.2(B) Q1201.1(G) R1241.1(A) U1.P8(GPIO_20_PWRCNTL_1)
GPIO_21: TP94.1 U1.P7(GPIO_21_BB_EN)
GPIO_22_CS: R16.1(A) U1.N8(GPIO_22_ROMCSB)
GPIO_22_ROMCSB_R: R16.2(B) R24.1(A) U2.1(CE_N)
GPIO_23: TP91.1 U1.N7(GPIO_23_CLKREQB)
GPU_DMINUS: C4004.2(B) U1.T2(DMINUS) U4001.4(D-)
GPU_DPLUS: C4004.1(A) U1.T4(DPLUS) U4001.3(D+)
HPD1: Q4402.2(E) R4409.1(A) U1.AC14(HPD1)
HPD1_A: D4406.1(K) MJ2501.19 R4410.2(B)
HPD4_IN: Q1602.1(B) R1618.1(A)
HPD_DPB: D4405.1(K) J2501.18(HOT_DET) R2527.2(B)
HPD_DVIEF: J1601.16(HOT_PLUG_DETECT) R1618.2(B)
JTAG_TCK: J4004.1(P1) NR75.2(B) U1.L3(JTAG_TCK)
JTAG_TDI: J4004.5(P5) U1.L5(JTAG_TDI)
JTAG_TDO: J4004.7(P7) U1.K4(JTAG_TDO)
JTAG_TMS: J4004.3(P3) U1.L1(JTAG_TMS)
JTAG_TRSTB: R38.2(B) R39.1(A) U1.L6(JTAG_TRSTB)
JTDIO_LOOP: MPCIE1.A6(JTAG3) MPCIE1.A7(JTAG4)
LDO1_FB: C865.2(B) MU861.7(FB) R864.1(A) R865.2(B) U861.7(FB)
LDO1_REFIN: MU861.5(REFIN) R866.2(B) U861.5(NC)
LDO1_VIN: C866.1(A) MR870.2(B) MR871.2(B) MR872.2(B) MR873.2(B) MU861.3(VIN) R870.2(B) R871.2(B) R872.2(B) R873.2(B) U861.3(VIN)
LDO2_FB: C855.2(B) R854.1(A) R855.2(B) U851.7(FB)
LDO2_VIN: C856.1(A) MR858.2(B) R858.2(B) U851.3(VIN)
LED: D4000.1(K) Q4050.3(C)
LED_ON: Q4050.1(B) R4058.1(A)
LED_PWR: D4000.2(A) R4059.1(A)
LM63_PWM: R4081.1(A) U4001.5(PWN)
M_DQMA#0: U1.E32(DQMA_0) U202.E7(DML)
M_DQMA#1: U1.E30(DQMA_1) U202.D3(DMU)
M_DQMA#2: U1.A21(DQMA_2) U201.E7(DML)
M_DQMA#3: U1.C21(DQMA_3) U201.D3(DMU)
M_DQMA#4: U1.E13(DQMA_4) U402.D3(DMU)
M_DQMA#5: U1.D12(DQMA_5) U402.E7(DML)
M_DQMA#6: U1.E3(DQMA_6) U401.D3(DMU)
M_DQMA#7: U1.F4(DQMA_7) U401.E7(DML)
M_MAA0: U1.K17(MAA_0) U201.N3(A0) U202.N3(A0) U401.N3(A0) U402.N3(A0)
M_MAA1: U1.J20(MAA_1) U201.P7(A1) U202.P7(A1) U401.P7(A1) U402.P7(A1)
M_MAA2: U1.H23(MAA_2) U201.P3(A2) U202.P3(A2) U401.P3(A2) U402.P3(A2)
M_MAA3: U1.G23(MAA_3) U201.N2(A3) U202.N2(A3) U401.N2(A3) U402.N2(A3)
M_MAA4: U1.G24(MAA_4) U201.P8(A4) U202.P8(A4) U401.P8(A4) U402.P8(A4)
M_MAA5: U1.H24(MAA_5) U201.P2(A5) U202.P2(A5) U401.P2(A5) U402.P2(A5)
M_MAA6: U1.J19(MAA_6) U201.R8(A6) U202.R8(A6) U401.R8(A6) U402.R8(A6)
M_MAA7: U1.K19(MAA_7) U201.R2(A7) U202.R2(A7) U401.R2(A7) U402.R2(A7)
M_MAA8: U1.J14(MAA_8) U201.T8(A8) U202.T8(A8) U401.T8(A8) U402.T8(A8)
M_MAA9: U1.K14(MAA_9) U201.R3(A9) U202.R3(A9) U401.R3(A9) U402.R3(A9)
M_MAA10: U1.J11(MAA_10) U201.L7(A10/AP) U202.L7(A10/AP) U401.L7(A10/AP) U402.L7(A10/AP)
M_MAA11: U1.J13(MAA_11) U201.R7(A11) U202.R7(A11) U401.R7(A11) U402.R7(A11)
M_MAA12: U1.H11(MAA_12) U201.N7(A12/BC_N) U202.N7(A12/BC_N) U401.N7(A12/BC_N) U402.N7(A12/BC_N)
M_MAA13: U1.G20(MAA_13) U201.T3(A13) U202.T3(A13) U401.T3(A13) U402.T3(A13)
M_MAA14: U1.G14(RSVD#7) U201.T7(A14) U202.T7(A14) U401.T7(A14) U402.T7(A14)
M_MDA0: U1.K27(DQA_0) U202.G2(DQL6)
M_MDA1: U1.J29(DQA_1) U202.H3(DQL4)
M_MDA2: U1.H30(DQA_2) U202.F2(DQL2)
M_MDA3: U1.H32(DQA_3) U202.E3(DQL0)
M_MDA4: U1.G29(DQA_4) U202.F7(DQL1)
M_MDA5: U1.F28(DQA_5) U202.F8(DQL3)
M_MDA6: U1.F32(DQA_6) U202.H8(DQL5)
M_MDA7: U1.F30(DQA_7) U202.H7(DQL7)
M_MDA8: U1.C30(DQA_8) U202.A2(DQU5)
M_MDA9: U1.F27(DQA_9) U202.C2(DQU3)
M_MDA10: U1.A28(DQA_10) U202.A3(DQU7)
M_MDA11: U1.C28(DQA_11) U202.C3(DQU1)
M_MDA12: U1.E27(DQA_12) U202.A7(DQU4)
M_MDA13: U1.G26(DQA_13) U202.B8(DQU6)
M_MDA14: U1.D26(DQA_14) U202.C8(DQU2)
M_MDA15: U1.F25(DQA_15) U202.D7(DQU0)
M_MDA16: U1.A25(DQA_16) U201.H8(DQL5)
M_MDA17: U1.C25(DQA_17) U201.H7(DQL7)
M_MDA18: U1.E25(DQA_18) U201.F7(DQL1)
M_MDA19: U1.D24(DQA_19) U201.F8(DQL3)
M_MDA20: U1.E23(DQA_20) U201.G2(DQL6)
M_MDA21: U1.F23(DQA_21) U201.E3(DQL0)
M_MDA22: U1.D22(DQA_22) U201.F2(DQL2)
M_MDA23: U1.F21(DQA_23) U201.H3(DQL4)
M_MDA24: U1.E21(DQA_24) U201.C8(DQU2)
M_MDA25: U1.D20(DQA_25) U201.B8(DQU6)
M_MDA26: U1.F19(DQA_26) U201.D7(DQU0)
M_MDA27: U1.A19(DQA_27) U201.A7(DQU4)
M_MDA28: U1.D18(DQA_28) U201.C3(DQU1)
M_MDA29: U1.F17(DQA_29) U201.A3(DQU7)
M_MDA30: U1.A17(DQA_30) U201.A2(DQU5)
M_MDA31: U1.C17(DQA_31) U201.C2(DQU3)
M_MDA32: U1.E17(DQA_32) U402.D7(DQU0)
M_MDA33: U1.D16(DQA_33) U402.C8(DQU2)
M_MDA34: U1.F15(DQA_34) U402.B8(DQU6)
M_MDA35: U1.A15(DQA_35) U402.A7(DQU4)
M_MDA36: U1.D14(DQA_36) U402.A3(DQU7)
M_MDA37: U1.F13(DQA_37) U402.C3(DQU1)
M_MDA38: U1.A13(DQA_38) U402.A2(DQU5)
M_MDA39: U1.C13(DQA_39) U402.C2(DQU3)
M_MDA40: U1.E11(DQA_40) U402.H8(DQL5)
M_MDA41: U1.A11(DQA_41) U402.F7(DQL1)
M_MDA42: U1.C11(DQA_42) U402.F8(DQL3)
M_MDA43: U1.F11(DQA_43) U402.H7(DQL7)
M_MDA44: U1.A9(DQA_44) U402.E3(DQL0)
M_MDA45: U1.C9(DQA_45) U402.F2(DQL2)
M_MDA46: U1.F9(DQA_46) U402.G2(DQL6)
M_MDA47: U1.D8(DQA_47) U402.H3(DQL4)
M_MDA48: U1.E7(DQA_48) U401.A3(DQU7)
M_MDA49: U1.A7(DQA_49) U401.A2(DQU5)
M_MDA50: U1.C7(DQA_50) U401.C3(DQU1)
M_MDA51: U1.F7(DQA_51) U401.C2(DQU3)
M_MDA52: U1.A5(DQA_52) U401.A7(DQU4)
M_MDA53: U1.E5(DQA_53) U401.B8(DQU6)
M_MDA54: U1.C3(DQA_54) U401.C8(DQU2)
M_MDA55: U1.E1(DQA_55) U401.D7(DQU0)
M_MDA56: U1.G7(DQA_56) U401.H3(DQL4)
M_MDA57: U1.G6(DQA_57) U401.G2(DQL6)
M_MDA58: U1.G1(DQA_58) U401.E3(DQL0)
M_MDA59: U1.G3(DQA_59) U401.F2(DQL2)
M_MDA60: U1.J6(DQA_60) U401.F7(DQL1)
M_MDA61: U1.J1(DQA_61) U401.H7(DQL7)
M_MDA62: U1.J3(DQA_62) U401.H8(DQL5)
M_MDA63: U1.J5(DQA_63) U401.F8(DQL3)
M_QSA0: U1.H28(RDQSA_0) U202.F3(DQSL)
M_QSA1: U1.C27(RDQSA_1) U202.C7(DQSU)
M_QSA2: U1.A23(RDQSA_2) U201.F3(DQSL)
M_QSA3: U1.E19(RDQSA_3) U201.C7(DQSU)
M_QSA4: U1.E15(RDQSA_4) U402.C7(DQSU)
M_QSA5: U1.D10(RDQSA_5) U402.F3(DQSL)
M_QSA6: U1.D6(RDQSA_6) U401.C7(DQSU)
M_QSA7: U1.G5(RDQSA_7) U401.F3(DQSL)
M_QSA#0: U1.H27(WDQSA_0) U202.G3(DQSL_N)
M_QSA#1: U1.A27(WDQSA_1) U202.B7(DQSU_N)
M_QSA#2: U1.C23(WDQSA_2) U201.G3(DQSL_N)
M_QSA#3: U1.C19(WDQSA_3) U201.B7(DQSU_N)
M_QSA#4: U1.C15(WDQSA_4) U402.B7(DQSU_N)
M_QSA#5: U1.E9(WDQSA_5) U402.G3(DQSL_N)
M_QSA#6: U1.C5(WDQSA_6) U401.B7(DQSU_N)
M_QSA#7: U1.H4(WDQSA_7) U401.G3(DQSL_N)
MEM_CALRN0: R302.1(A) R303.1(A) U1.J25(MEM_CALRN0)
MEM_CALRP0: R301.1(A) R303.2(B) U1.K25(MEM_CALRP0)
MVDD_BOOT: C705.1(A) D701.1(K) U701.1(BOOT)
MVDD_EN: C711.1(A) C712.1(A) Q842.3(C) U701.7(COMP)
MVDD_FB: R710.1(A) R711.1(A) R713.1(A) R714.1(A) U701.6(FB)
MVDD_FB_TRACE: NS700.2(N2) R700.1(A)
MVDD_LGATE: Q703.4(G4) R722.2(B)
MVDD_LGATE_CTR: R715.1(A) R722.1(A) U701.4(LGATE)
MVDD_PHASE: C705.2(B) L701.1 Q701.1(S1) Q701.2(S2) Q701.3(S3) Q703.5(D5) Q703.6(D6) Q703.7(D7) Q703.8(D8) Q703.9(D9) R719.1(A) U701.8(PHASE)
MVDD_SV: C713.1(A) R700.2(B) R711.2(B)
MVDD_UGATE: Q701.4(G4) R721.2(B)
MVDD_UGATE_CTR: R721.1(A) U701.2(UGATE)
MVDD_VCC: C703.1(A) R707.2(B) U701.5(VCC)
MVREFD_A: C295.1(A) R291.2(B) R292.1(A) U1.K26(MVREFDA)
MVREFS_A: C297.1(A) R293.2(B) R294.1(A) U1.J26(MVREFSA)
NFB: Q4102.1(B) R4107.1(A) R4108.1(A)
ODTA0: R225.1(A) R226.2(B) R229.2(B) U201.K1(ODT) U202.K1(ODT)
ODTA0_R: R226.1(A) U1.L18(ODTA0)
ODTA1: R227.1(A) R228.2(B) R230.2(B) U401.K1(ODT) U402.K1(ODT)
ODTA1_R: R228.1(A) U1.K16(ODTA1)
PCIE_CALRN: R8.2(B) U1.AA22(PCIE_CALRN)
PCIE_CALRP: R9.1(A) U1.Y22(PCIE_CALRP)
PCIE_REFCLKN: MPCIE1.A14(REFCLK-) U1.AK32(PCIE_REFCLKN)
PCIE_REFCLKP: MPCIE1.A13(REFCLK+) U1.AK30(PCIE_REFCLKP)
PCIE_TX0N: C4.1(A) U1.AG31(PCIE_TX0N)
PCIE_TX0P: C3.1(A) U1.AH30(PCIE_TX0P)
PCIE_TX1N: C6.1(A) U1.AF28(PCIE_TX1N)
PCIE_TX1P: C5.1(A) U1.AG29(PCIE_TX1P)
PCIE_TX2N: C9.1(A) U1.AF26(PCIE_TX2N)
PCIE_TX2P: C7.1(A) U1.AF27(PCIE_TX2P)
PCIE_TX3N: C11.1(A) U1.AD26(PCIE_TX3N)
PCIE_TX3P: C10.1(A) U1.AD27(PCIE_TX3P)
PCIE_TX4N: C13.1(A) U1.AB25(PCIE_TX4N)
PCIE_TX4P: C12.1(A) U1.AC25(PCIE_TX4P)
PCIE_TX5N: C16.1(A) U1.Y24(PCIE_TX5N)
PCIE_TX5P: C15.1(A) U1.Y23(PCIE_TX5P)
PCIE_TX6N: C18.1(A) U1.AB26(PCIE_TX6N)
PCIE_TX6P: C17.1(A) U1.AB27(PCIE_TX6P)
PCIE_TX7N: C22.1(A) U1.Y26(PCIE_TX7N)
PCIE_TX7P: C19.1(A) U1.Y27(PCIE_TX7P)
PCIE_TX8N: C24.1(A) U1.W23(PCIE_TX8N)
PCIE_TX8P: C23.1(A) U1.W24(PCIE_TX8P)
PCIE_TX9N: C26.1(A) U1.U26(PCIE_TX9N)
PCIE_TX9P: C25.1(A) U1.V27(PCIE_TX9P)
PCIE_TX10N: C29.1(A) U1.U23(PCIE_TX10N)
PCIE_TX10P: C28.1(A) U1.U24(PCIE_TX10P)
PCIE_TX11N: C31.1(A) U1.T27(PCIE_TX11N)
PCIE_TX11P: C30.1(A) U1.T26(PCIE_TX11P)
PCIE_TX12N: C36.1(A) U1.T23(PCIE_TX12N)
PCIE_TX12P: C32.1(A) U1.T24(PCIE_TX12P)
PCIE_TX13N: C38.1(A) U1.P26(PCIE_TX13N)
PCIE_TX13P: C37.1(A) U1.P27(PCIE_TX13P)
PCIE_TX14N: C40.1(A) U1.P23(PCIE_TX14N)
PCIE_TX14P: C39.1(A) U1.P24(PCIE_TX14P)
PCIE_TX15N: C42.1(A) U1.N26(PCIE_TX15N)
PCIE_TX15P: C41.1(A) U1.M27(PCIE_TX15P)
PERN0: C4.2(B) MPCIE1.A17(PERN0)
PERN1: C6.2(B) MPCIE1.A22(PERN1)
PERN2: C9.2(B) MPCIE1.A26(PERN2)
PERN3: C11.2(B) MPCIE1.A30(PERN3)
PERN4: C13.2(B) MPCIE1.A36(PERN4)
PERN5: C16.2(B) MPCIE1.A40(PERN5)
PERN6: C18.2(B) MPCIE1.A44(PERN6)
PERN7: C22.2(B) MPCIE1.A48(PERN7)
PERN8: C24.2(B) MPCIE1.A53(PERN8)
PERN9: C26.2(B) MPCIE1.A57(PERN9)
PERN10: C29.2(B) MPCIE1.A61(PERN10)
PERN11: C31.2(B) MPCIE1.A65(PERN11)
PERN12: C36.2(B) MPCIE1.A69(PERN12)
PERN13: C38.2(B) MPCIE1.A73(PERN13)
PERN14: C40.2(B) MPCIE1.A77(PERN14)
PERN15: C42.2(B) MPCIE1.A81(PERN15)
PERP0: C3.2(B) MPCIE1.A16(PERP0)
PERP1: C5.2(B) MPCIE1.A21(PERP1)
PERP2: C7.2(B) MPCIE1.A25(PERP2)
PERP3: C10.2(B) MPCIE1.A29(PERP3)
PERP4: C12.2(B) MPCIE1.A35(PERP4)
PERP5: C15.2(B) MPCIE1.A39(PERP5)
PERP6: C17.2(B) MPCIE1.A43(PERP6)
PERP7: C19.2(B) MPCIE1.A47(PERP7)
PERP8: C23.2(B) MPCIE1.A52(PERP8)
PERP9: C25.2(B) MPCIE1.A56(PERP9)
PERP10: C28.2(B) MPCIE1.A60(PERP10)
PERP11: C30.2(B) MPCIE1.A64(PERP11)
PERP12: C32.2(B) MPCIE1.A68(PERP12)
PERP13: C37.2(B) MPCIE1.A72(PERP13)
PERP14: C39.2(B) MPCIE1.A76(PERP14)
PERP15: C41.2(B) MPCIE1.A80(PERP15)
PERST#: MPCIE1.A11(PERST_) R61.1(A) U4.2(B)
PERST#_BUF: D4400.2(K) R61.2(B) R4054.1(A) U1.AL27(PERSTB) U4.4(Y)
PERST#_CTFIN: Q4013.1(B) R4054.2(B) R4061.2(B)
PETN0_GFXRN0: MPCIE1.B15(PETN0) TP102.1 U1.AE31(PCIE_RX0N)
PETN1_GFXRN1: MPCIE1.B20(PETN1) U1.AD28(PCIE_RX1N)
PETN2_GFXRN2: MPCIE1.B24(PETN2) TP104.1 U1.AC31(PCIE_RX2N)
PETN3_GFXRN3: MPCIE1.B28(PETN3) TP106.1 U1.AB28(PCIE_RX3N)
PETN4_GFXRN4: MPCIE1.B34(PETN4) U1.AA31(PCIE_RX4N)
PETN5_GFXRN5: MPCIE1.B38(PETN5) TP108.1 U1.Y28(PCIE_RX5N)
PETN6_GFXRN6: MPCIE1.B42(PETN6) TP110.1 U1.W31(PCIE_RX6N)
PETN7_GFXRN7: MPCIE1.B46(PETN7) U1.V28(PCIE_RX7N)
PETN8_GFXRN8: MPCIE1.B51(PETN8) TP112.1 U1.U31(PCIE_RX8N)
PETN9_GFXRN9: MPCIE1.B55(PETN9) TP114.1 U1.T28(PCIE_RX9N)
PETN10_GFXRN10: MPCIE1.B59(PETN10) U1.R31(PCIE_RX10N)
PETN11_GFXRN11: MPCIE1.B63(PETN11) TP116.1 U1.P28(PCIE_RX11N)
PETN12_GFXRN12: MPCIE1.B67(PETN12) TP118.1 U1.N31(PCIE_RX12N)
PETN13_GFXRN13: MPCIE1.B71(PETN13) U1.M28(PCIE_RX13N)
PETN14_GFXRN14: MPCIE1.B75(PETN14) TP120.1 U1.L31(PCIE_RX14N)
PETN15_GFXRN15: MPCIE1.B79(PETN15) TP122.1 U1.K30(PCIE_RX15N)
PETP0_GFXRP0: MPCIE1.B14(PETP0) TP101.1 U1.AF30(PCIE_RX0P)
PETP1_GFXRP1: MPCIE1.B19(PETP1) U1.AE29(PCIE_RX1P)
PETP2_GFXRP2: MPCIE1.B23(PETP2) TP103.1 U1.AD30(PCIE_RX2P)
PETP3_GFXRP3: MPCIE1.B27(PETP3) TP105.1 U1.AC29(PCIE_RX3P)
PETP4_GFXRP4: MPCIE1.B33(PETP4) U1.AB30(PCIE_RX4P)
PETP5_GFXRP5: MPCIE1.B37(PETP5) TP107.1 U1.AA29(PCIE_RX5P)
PETP6_GFXRP6: MPCIE1.B41(PETP6) TP109.1 U1.Y30(PCIE_RX6P)
PETP7_GFXRP7: MPCIE1.B45(PETP7) U1.W29(PCIE_RX7P)
PETP8_GFXRP8: MPCIE1.B50(PETP8) TP111.1 U1.V30(PCIE_RX8P)
PETP9_GFXRP9: MPCIE1.B54(PETP9) TP113.1 U1.U29(PCIE_RX9P)
PETP10_GFXRP10: MPCIE1.B58(PETP10) U1.T30(PCIE_RX10P)
PETP11_GFXRP11: MPCIE1.B62(PETP11) TP115.1 U1.R29(PCIE_RX11P)
PETP12_GFXRP12: MPCIE1.B66(PETP12) TP117.1 U1.P30(PCIE_RX12P)
PETP13_GFXRP13: MPCIE1.B70(PETP13) U1.N29(PCIE_RX13P)
PETP14_GFXRP14: MPCIE1.B74(PETP14) TP119.1 U1.M30(PCIE_RX14P)
PETP15_GFXRP15: MPCIE1.B78(PETP15) TP121.1 U1.L29(PCIE_RX15P)
PFB: C4100.1(A) D4100.2(A) Q4101.1(B) R4103.2(B)
PRESENCE: MPCIE1.A1(PRSNT1_A1) MPCIE1.B81(PRSNT2_B81)
PSEQ_LDO_EN: Q841.1(B) R845.1(A)
PSEQ_MVDD_EN: Q842.1(B) R846.1(A)
PSEQ_N1: C846.1(A) Q850.3(C) Q852.1(B) R857.2(B)
PSEQ_N2: Q851.1(B) R850.2(B) R851.1(A)
PSEQ_N3: Q850.1(B) R852.1(A) R853.1(A)
PSEQ_VDDCUP: C841.1(A) Q840.1(B) R841.2(B)
PWM_B: Q4011.3(C) Q4100.3(C) R4102.2(B) R4103.1(A) R4111.1(A)
PWM_ENB: C4402.1(A) Q4011.1(B) R4057.1(A) R4063.1(A)
PWM_R: Q4100.1(B) R4101.2(B)
PWR_ENABLE#: Q840.3(C) R843.1(A) R845.2(B) R846.2(B)
PWRGOOD_GPU: R59.2(B) R60.1(A) U1.N10(PWRGOOD)
PX_EN: R7.2(B) U1.AB16(PX_EN)
R2SET: R23.1(A) U1.AG13(SWAPLOCKA)
R_DAC2: C2001.1(A) L2001.1(A) MR1015.2(B) R2003.1(A)
RASA#0: U1.G22(RASA0B) U201.J3(RAS_N) U202.J3(RAS_N)
RASA#1: U1.G17(RASA1B) U401.J3(RAS_N) U402.J3(RAS_N)
RB_DAC2: MR1027.2(B) R2027.1(A)
REST_CTF: D4400.3(COM) R4400.1(A) R4401.1(A) R4402.2(B)
RSET: R12.2(B) U1.AD22(RSET)
SCL: R33.1(A) R597.1(A) U1.R1(SCL)
SCL_R: R4001.2(B) U4001.10(SMBCLK)
SDA: R34.1(A) R596.1(A) U1.R3(SDA)
SDA_R: R4002.2(B) U4001.9(SMBDAT)
SMCLK: MPCIE1.B5(SMCLK) Q2.3(D) R4.2(B)
SMDAT: MPCIE1.B6(SMDAT) Q1.3(D) R3.2(B)
SS_SEL0: MR71.2(B) R71.1(A) U12.7(SS_SEL0)
SS_SEL1: MR70.2(B) R70.1(A) U12.3(SS_SEL1)
SWAPLOCKB: TP123.1 U1.AH12(SWAPLOCKB)
TCRIT: R4065.1(A) U4001.1(TCRIT_N)
TESTEN: J4004.2(P2) R37.1(A) R436.2(B) U1.K7(TESTEN)
TESTEN_LEGACY: R35.1(A) U1.AF24(RSVD#AF24)
THERMINT: R4080.2(B) U4001.7(ALERT_N)
TMDP_EN: C843.1(A) Q1601.1(G) Q2701.1(G) R844.2(B)
TS_FDO: R4081.2(B) R4100.2(B) R4101.1(A) U1.R5(TS_FDO)
UNNAMED_1_RES_I16_A: R63.1(A) R65.2(B) U4.1(A)
UNNAMED_4_CAP_I24_A: C499.1(A) R221.2(B) R222.1(A)
UNNAMED_4_CAP_I139_A: C500.1(A) R223.2(B) R224.1(A)
UNNAMED_4_DDR364MX1623E22387M_1: R218.1(A) U202.L8(ZQ)
UNNAMED_4_DDR364MX1623E22387M_2: R217.1(A) U201.L8(ZQ)
UNNAMED_4_DDR364MX1623E22387M_3: R219.1(A) U401.L8(ZQ)
UNNAMED_4_DDR364MX1623E22387MNG: R220.1(A) U402.L8(ZQ)
UNNAMED_5_CAP_I72_A: C82.1(A) R30.2(B) R31.1(A) Y2.1(A)
UNNAMED_5_CAP_I92_B: C94.2(B) R296.1(A)
UNNAMED_5_CAP_I102_B: C95.2(B) R297.1(A)
UNNAMED_5_RES_I15_B: MR75.2(B) R36.2(B) R75.2(B) R76.2(B)
UNNAMED_6_CAP_I32_A: C1002.1(A) L1002.1(A) R1016.2(B)
UNNAMED_6_CAP_I51_A: C1001.1(A) L1001.1(A) R1015.2(B)
UNNAMED_6_CAP_I68_A: C1003.1(A) L1003.1(A) R1017.2(B)
UNNAMED_7_NPN_I43_B: Q2513.1(B) Q4402.1(B) R2527.1(A) R4410.1(A)
UNNAMED_11_CAP_I2_B: C612.2(B) R609.2(B) R612.1(A) R614.2(B)
UNNAMED_11_CAP_I4_B: C611.2(B) R612.2(B)
UNNAMED_11_CAP_I11_B: C608.2(B) R619.1(A)
UNNAMED_11_CAP_I15_B: C613.2(B) R613.2(B)
UNNAMED_12_CAP_I15_B: C712.2(B) R709.2(B) R712.1(A) R714.2(B)
UNNAMED_12_CAP_I19_A: C708.1(A) R719.2(B)
UNNAMED_12_CAP_I22_B: C711.2(B) R712.2(B)
UNNAMED_12_CAP_I23_B: C713.2(B) R713.2(B)
UNNAMED_13_2480063100GUP7701_I1: R856.1(A) U851.5(NC)
UNNAMED_14_NPN_I18_E: Q850.2(E) Q851.3(C)
UNNAMED_15_MOSN_I38_D: Q4014.3(D) R4056.1(A)
UNNAMED_15_MOSN_I38_G: Q4013.3(C) Q4014.1(G) Q4016.3(C) R4055.1(A)
UNNAMED_15_NPN_I34_B: Q4016.1(B) R4060.2(B)
UNNAMED_15_NPN_I128_C: Q4401.3(C) R4405.2(B)
UNNAMED_15_PNP_I17_E: Q4101.2(E) Q4102.2(E) R4105.2(B)
UNNAMED_15_PNP_I27_C: Q4008.3(C) R4045.1(A) R4050.2(B)
UNNAMED_15_RES_I36_A: D4100.1(K) R4112.2(B) R4113.1(A)
UNNAMED_16_RES_I36_B: R595.2(B) TP500.1
UNNAMED_16_RES_I44_A: NR4000.1(A) SW4002.4(A2)
VDIFF: C4102.1(A) Q4101.3(C) Q4103.1(B) R4106.1(A)
VREFC_U201: C413.1(A) R201.2(B) R202.1(A) U201.M8(VREFCA)
VREFC_U202: C438.1(A) R203.2(B) R204.1(A) U202.M8(VREFCA)
VREFC_U401: C463.1(A) R205.2(B) R206.1(A) U401.M8(VREFCA)
VREFC_U402: C448.1(A) R207.2(B) R208.1(A) U402.M8(VREFCA)
VREFD_U201: C486.1(A) R209.2(B) R210.1(A) U201.H1(VREFDQ)
VREFD_U202: C487.1(A) R211.2(B) R212.1(A) U202.H1(VREFDQ)
VREFD_U401: C488.1(A) R213.2(B) R214.1(A) U401.H1(VREFDQ)
VREFD_U402: C489.1(A) R215.2(B) R216.1(A) U402.H1(VREFDQ)
VREFG: C53.2(B) R21.2(B) R22.2(B) U1.AC16(VREFG)
WEA#0: U1.G25(WEA0B) U201.L3(WE_N) U202.L3(WE_N)
WEA#1: U1.H10(WEA1B) U401.L3(WE_N) U402.L3(WE_N)
XIN_OSC: C92.1(A) U12.1(XTALIN) Y3.3(P4)
XO_IN: TR75.2(B) U1.AC22(XO_IN)
XO_IN2: R74.2(B) U1.AB22(XO_IN2)
XOUT_OSC: C93.1(A) U12.10(XTALOUT) Y3.1(P1)
XTALIN: R30.1(A) R36.1(A) U1.AM28(XTALIN)
XTALOUT: C83.1(A) R31.2(B) U1.AK28(XTALOUT) Y2.2(B)
N857905: Q1803.1(B) Q1804.3(D) R1805.2(B)
N7393636: C411.1 F400.2 R4411.2(B) R4412.2(B) R4413.2(B) UNK+5V.1
N7393760: F400.1 U403.3(OUT)

Pads without a net: D1603 1 2 9 10; D4400 1; J4004 6; MJ1001 4 11; MJ2501 14; MPCIE1 A5 A8 A19 A32 A33 A50 B9 B10 B11 B12 B17 B30 B31 B48 B82; SW4002 2; U1 AA3 AB2 AB4 AB7 AB8 AB9 AB11 AB12 AC7 AC8 AC10 AD2 AD4 AD7 AD9 AD19 AE8 AE9 AE17 AE20 AH20 AJ9 AJ11 AJ19 AJ23 AK10 AK12 AK18 AK24 AL9 AL11 AL19 AM10 AM12 J22 K13 L9 L16 L17 N9 U5 V2 V4 W3 W5 Y2 Y4 Y7 Y8; U201 J1 J9 L1 L9 M7; U202 J1 J9 L1 L9 M7; U401 J1 J9 L1 L9 M7; U402 J1 J9 L1 L9 M7; U1999 8 9 10 11 12 13; U4001 8; U4050 4 5 10 12 14; Y3 2 4

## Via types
v1: diameter 0.5, hole 0.25, TOP to BOTTOM, 667 vias
v2: diameter 0.9, hole 0.43, TOP to BOTTOM, 191 vias
v3: diameter 0.55, hole 0.25, TOP to BOTTOM, 731 vias
v4: diameter 0.8, hole 0.4, TOP to BOTTOM, 129 vias
v5: diameter 0.7, hole 0.25, TOP to BOTTOM, 7 vias

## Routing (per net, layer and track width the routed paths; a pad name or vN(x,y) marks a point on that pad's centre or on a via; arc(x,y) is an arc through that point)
+1.8V: length 148.4
  TOP w0.3: 86.25,56.09 85.76,55.6 U1.AB21 ; 86.25,56.09 85.75,56.59 U1.AB20 ; 86.25,56.09 86.75,56.59 U1.AA20 ; 86.25,56.09 v1(86.25,56.1) ; 86.25,56.09 86.74,55.6 U1.AA21 ; U1.AE26 v1(82.95,51.8) ; v1(82.95,51.8) U1.AE25 v1(83.75,52.6) ; v1(82.95,51.8) U1.AF25 U1.AG26 ; v1(83.75,52.6) U1.AD24 U1.AC23 84.98,53.8 85.26,54.08 85.39,54.08 v1(85.42,54.05) 85.67,53.8 U1.AB23 ; v1(83.75,52.6) U1.AE24 ; U1.U12 89.72,62.4 v1(89.22,62.9) 88.75,62.43 U1.V12 U1.Y12 ; v1(84.54,59.09) 84.41,58.97 84.41,58.69 84.15,58.43 U1.AD17
  TOP w0.4: U1.Y12 87.75,62.45 v1(87.25,62.95)
  TOP w0.5: 85.5,76.28 v3(85.5,72.16) ; 85.5,76.28 84.27,76.28 82.05,78.5 79.85,78.5 79.45,78.1 75.49,78.1 73.7,79.89 73.7,81.91 72.55,83.07 72.55,85.4 71.55,86.4 70.05,86.4 68.3,84.65 66.3,84.65 62.35,80.7 v3(62.05,80.7) ; 85.5,76.28 86.79,77.57 87.55,77.57 88.23,76.9 88.23,76.8 v3(88.54,76.48)
  L3_INNER w0.4: v1(72.67,60.62) 74.52,58.78 79.41,58.78 80.23,59.6 81.55,59.6 82,59.15 82.58,59.15 83.03,59.6 84.05,59.6 84.54,59.11 v1(84.54,59.09)
  L3_INNER w0.5: v3(53.75,63.4) 57.75,59.4 63.65,59.4 66.65,56.4 v3(66.65,53.6)
  BOTTOM w0.3: C4020.1 84.78,58.61 84.54,58.84 v1(84.54,59.09) ; v1(82.95,51.8) 83.06,51.8 83.75,52.48 v1(83.75,52.6)
  BOTTOM w0.4: v1(89.22,62.9) 89.69,62.42 C143.1 ; v1(86.25,56.1) 86.25,56.02 85.42,55.19 85.41,55.19 85.41,54.06 v1(85.42,54.05) ; v1(87.25,62.95) 87.8,63.5 R59.1 87.8,63.75 87.54,64.01 87.49,64.01 87.24,64.26 87.24,64.43 87.2,64.47 87.2,66.24 87.21,66.25 87.21,66.7 87.24,66.74 B800.1 87.24,69.2 86.63,69.81 86.24,69.81 85.24,70.81 C156.1 85.24,71.91 v3(85.5,72.16)
  BOTTOM w0.5: v3(53.75,63.4) 53.75,64.97 56.25,67.47 56.25,73.87 62.02,79.63 62.02,80.67 v3(62.05,80.7) ; 78.86,49.6 79.5,50.24 79.8,50.24 80.41,50.85 80.41,50.87 81.33,51.8 v1(82.95,51.8) ; 78.86,49.6 78.75,49.71 ; 78.86,49.6 C161.1 ; v3(88.54,76.48) 88.72,76.48 89.56,77.32 89.56,79.92 91.75,82.11 91.75,82.15 92.12,82.51 94.4,82.51 96.63,80.28 B5.1 96.53,78.69 C144.1 B12.1 ; R72.2 86.81,61.58 86.81,62.51 v1(87.25,62.95)
+1.8V_LDO_EN: length 150.2
  TOP w0.1: v3(53.85,25.25) 55.6,25.25 57.02,26.67 57.02,33.2 57.62,33.8 v3(57.62,39.9) ; v3(127.85,103.3) 127.85,105.5 128.35,106 Q841.3
  BOTTOM w0.1: v3(127.85,103.3) 125.39,100.84 116.92,100.84 116.59,100.51 111.51,100.51 111.07,100.95 91.24,100.95 85.97,95.68 75.67,95.68 72.05,92.06 72.05,85.37 71.55,84.86 70.18,84.86 68.08,86.97 65.82,86.97 63.87,85.01 63.87,80.07 57.62,73.83 v3(57.62,39.9) ; U861.2 53.05,26.82 R862.2 53.19,24.59 v3(53.85,25.25)
+1.8V_LDO_POK: length 3.6
  BOTTOM w0.1: U861.1 54.35,26.84 R863.2 R839.1
+1V: length 133.1
  TOP w0.4: v3(93.7,53.4) 94.1,53 U1.L24 v1(94.88,52.48) 94.6,52.2 U1.L25 94.35,52.13 94.45,52.03 94.45,51.57 94.35,51.47 U1.L26 ; v3(93.7,53.4) 93.3,53.8 U1.N23 93.15,53.95 93.55,54.35 U1.M22 93.15,55 93.05,55 v3(93.05,55.05) 92.6,54.6 U1.N22 92.11,55.04 v1(92.03,55.04) 91.59,54.6 U1.R22 91.35,54.41 90.75,54.41 U1.T22 U1.U22 v1(89.25,55.1) U1.V22 ; v3(93.7,53.4) 94.1,53.8 U1.L23 ; v3(93.7,53.4) 93.3,53 U1.N24
  TOP w0.5: v3(97.94,81.1) 96.44,79.6 96.44,78.99 95.73,78.28 v3(95.73,77.01) ; v3(85.85,81.1) 80.27,81.1 78.57,82.8 73.77,82.8 73.15,83.42 73.15,85.65 71.8,87 69.35,87 v3(69.05,86.7) ; v3(87.45,76.7) B801.1 87.62,75.82 88.93,75.82 89.18,76.07 89.18,76.91 88.67,77.42 v3(88.65,77.42)
  L3_INNER w0.4: v3(77.22,54.63) 77.85,54 80.29,54 81.08,54.8 82.54,54.8 82.59,54.84 83.89,54.84 84.45,55.4 86.05,55.4 v1(86.31,55.14)
  BOTTOM w0.4: 93.04,55.04 v3(93.05,55.05) ; 93.04,55.04 C151.1 93.09,54.35 93.62,53.82 93.62,53.64 93.62,53.64 93.62,53.48 v3(93.7,53.4) 93.76,53.4 C150.1 94.42,52.93 v1(94.88,52.48) ; 93.04,55.04 93.04,55.04 v1(92.03,55.04) ; v1(89.25,55.1) 89.25,54.97 88.77,54.48 ; v1(86.31,55.14) 87.08,54.37 R8.1 87.25,54.49 87.5,54.49 87.53,54.52 88.74,54.52 88.77,54.48 ; 88.77,54.48 89.2,54.05 C153.1 90.53,54.05 C152.1 ; v3(95.73,77.01) 95.73,74.95 94.62,73.84 94.62,72.49 94.15,72.02 94.15,70.89 B9.1
  BOTTOM w0.5: 67.71,62.78 68.53,63.6 69.8,63.6 71.23,65.03 71.25,65.03 72.27,66.06 73.19,66.06 74.46,67.33 74.86,67.33 76.42,68.89 B2505.1 78.02,69.74 v3(78.02,70.25) ; v3(85.85,81.1) 86.05,81.1 86.83,80.32 86.83,79.01 87.22,78.61 87.22,76.93 v3(87.45,76.7) ; v3(97.94,81.1) 97.94,81.33 95.99,83.29 92.02,83.29 88.93,80.19 88.93,77.7 v3(88.65,77.42) ; v3(56.78,64.74) 57.02,64.98 57.02,73.79 63.47,80.24 63.47,85.2 65.77,87.5 68.25,87.5 v3(69.05,86.7)
  vias: v1(65.8,61.08) v1(66.77,61.05) v3(55.12,64.74) v3(55.92,64.74) v3(72.09,55.58) v3(72.75,55.96) v3(72.74,55.19)
+1V_LDO_EN: length 35.2
  TOP w0.1: v3(45.75,29.2) 46.95,28 52.15,28 53.32,26.83 53.32,23.63 53.85,23.1 v3(56.35,23.1)
  BOTTOM w0.1: R839.2 R849.2 56.44,23.1 v3(56.35,23.1) ; U851.2 42.21,43.97 41.45,43.2 41.45,35.2 45.75,30.9 v3(45.75,29.2)
+1V_LDO_POK: length 46.1
  TOP w0.1: R65.1 60.25,23.9 58.9,25.25 58.9,29.45 60.32,30.88 v3(60.32,39.04)
  BOTTOM w0.1: U851.1 43.41,41.35 R859.2 43.26,40.79 43.84,40.21 56.08,40.21 57.18,39.12 60.25,39.12 v3(60.32,39.04)
+3.3V_BUS: length 305
  TOP w0.3: R4100.1 73.86,88.89 75.15,90.19 U4001.2
  TOP w0.4: R4075.1 61.05,90.44 61.05,96 61.06,96.01 v1(61.06,96.09) ; MR4076.1 v3(64.29,96.1) ; v3(69.03,59.98) 69.03,59.93 68.59,59.48 R43.1 68.35,59.49 R56.1 ; R4100.1 v3(73.86,87.6)
  TOP w0.5: R53.1 v3(78.75,90.6) ; U2.3 v3(81.35,89.97) ; R1.1 55.64,17.26 v3(55.93,17.55) ; v3(52.58,25.58) 52.58,26.47 51.75,27.3 v3(45.75,27.3) ; R4017.1 v3(72.77,99.59) ; R4040.1 117.45,99.29 v3(117.34,99.29) ; v3(111.83,101.2) 111.83,102.59 R4056.2 ; Q2513.3 19.8,70.15 v3(20.15,70.5) 20.99,71.34 22.48,71.34 23.05,71.91 Q4402.3 25.51,72.34 26.95,70.9 v3(33.6,70.9) ; v2(52.95,7.15) 52.65,6.85 MPCIE1.B8 ; R4059.2 C57.1 89.21,103.79 88,102.59 v3(88,100.38) ; R2523.1 v3(31.85,86.3) ; R34.2 v3(89.75,84.4) ; v3(58.89,21.93) Q1.1 ; R63.2 v3(58.45,11.7) ; v3(52.85,22.1) 52.52,21.77 52.52,20.26 R2.1 ; R4011.1 v3(75.06,99.57) ; v3(86.45,87.1) 87.25,86.3 R44.1 ; U2.8 v3(89.99,92.5) ; U1.AA17 U1.AB18 v1(86.25,57.1) U1.AA18 U1.AB17 ; Q4008.2 v3(116.2,101.2) ; R49.1 v3(95.05,91.8) ; R38.1 105.1,93.04 106.58,93.04 v3(106.78,92.84) ; R55.1 v3(98.25,91.8) ; R33.2 v3(89.75,85.3) ; C4014.1 v3(117.92,101.47) ; R4050.1 v3(101.27,97.23) ; R24.2 v3(78.75,91.5) ; R45.1 v3(87.55,81.29) R58.1 ; v3(65.85,77.1) 44.11,77.1 v3(40.49,80.72) ; v3(102.48,100.33) Q4400.2 102.19,104.06 98.35,107.9 R4407.1 ; R1241.2 v3(82.89,85.32) ; U2.7 v3(89.99,91.23) ; v3(55.09,21.74) Q2.1 ; R1240.2 v3(96.05,91.8) ; C4013.1 v3(119.07,101.47) ; R50.1 v3(93.85,91.8) ; C4003.1 v3(90.55,92) ; R48.1 v3(97.05,91.8) ; R57.1 v3(74.15,84.3) ; R4018.1 v3(73.91,99.57)
  L3_INNER w0.4: v3(83.72,54.23) 81.58,54.23 75.46,48.11 75.46,43.33 73.63,41.5 61.21,41.5
  L3_INNER w0.5: v1(64.36,63.35) 61.6,63.35 58.05,66.9 49.35,66.9 48.25,65.8
  BOTTOM w0.4: R436.1 101.45,89.56 100.97,90.04 v3(100.97,91.29) ; C167.1 86.94,74.33 86.62,74.64 v1(86.62,75.88) 86.02,75.88 R595.1 ; C165.1 85.86,57.14 ; 85.86,57.14 86.23,57.12 v1(86.25,57.1) 86.75,57.6 C164.1 ; 85.86,57.14 85.16,57.14 84.86,56.85 84.86,56.39 84.71,56.24 84.71,54.51 84.51,54.31 83.79,54.31 v3(83.72,54.23)
  BOTTOM w0.5: v3(82.89,85.32) 82.89,84.54 79.65,81.3 79.65,79 79.17,78.52 79.17,76.15 80.13,75.19 C4001.1 80.47,75.43 C4002.1 ; v3(53.75,24.08) 53.27,23.61 R862.1 ; R849.1 v3(56.95,25.5) ; v3(69.03,59.98) 69.03,58.98 68.5,58.45 v3(61.44,58.45) ; v3(86.45,87.1) 88.25,85.3 v3(89.75,85.3) v3(89.75,84.4) 87.55,82.2 v3(87.55,81.29) ; Q1602.3 32.49,21.04 33.35,21.9 33.35,23.3 32.81,23.84 R52.1 31.47,23.85 R51.1 33.11,24.86 34.65,26.4 38.35,26.4 39.25,27.3 v3(45.75,27.3) ; B72.1 R71.2 64.05,65.09 64.05,63.66 v1(64.36,63.35) 64.45,63.44 64.45,63.67 65.22,64.44 66.78,64.44 v3(66.95,64.6) 67.59,65.24 B71.1 ; J4004.8 v3(106.48,94.31) ; v3(95.05,91.8) 95.05,88.56 R46.1 ; v3(55.02,24.03) 54.6,23.61 R863.1 ; NR4000.2 91.47,99.16 v3(90.65,98.35) ; R70.2 73.19,70.44 73.65,70.9 73.65,73.6 73.11,74.14 66.9,74.14 65.85,75.2 v3(65.85,77.1) ; R47.1 93.85,89.43 v3(93.85,91.8) ; v3(20.15,70.5) 21.25,71.6 R850.1 ; v3(52.95,42.1) 51.65,40.8 44.64,40.8 R859.1 ; v3(85.25,86.3) 85.25,83.8 84.65,83.2 84.65,79.94 86.62,77.97 v1(86.62,75.88) ; R54.1 87.91,72.97 86.94,73.94 C167.1
  vias: v2(52.95,11.1) v2(52.95,9.8) v2(52.95,8.5) v2(53.55,12.2) v2(54.45,11.1) v2(54.45,9.8) v2(54.45,8.5) v2(54.45,7.1) v3(10.65,97.8) v3(10.65,97) v3(10.65,96.1) v3(34.52,70.87) v3(35.48,70.87) v3(36.4,70.87) v3(84.45,93.31) v3(85.25,93.31) v3(86.31,93.31) v3(87.11,93.31) v3(87.91,93.31) v3(88.9,93.32) v3(89.84,93.32)
